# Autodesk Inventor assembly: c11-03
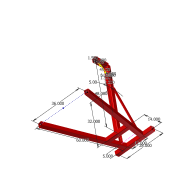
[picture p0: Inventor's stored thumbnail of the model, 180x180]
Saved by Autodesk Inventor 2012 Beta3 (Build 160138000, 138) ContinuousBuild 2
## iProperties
Created: 2011-01
Part Number: c11-03
Document SubType Name: Assembly
Designer: Beta-8540w
_SolveAssemblyDoc: Frame Generator Solve Assembly
_Version: 15.0.0
Author: Beta-8540w
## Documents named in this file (3)
- C:\Inventor 2012 Essentials\Assemblies\Chapter 11\c11-03.iam
- C:\Inventor 2012 Essentials\Parts\Chapter 11\c11-01.ipt
- C:\Inventor 2012 Essentials\Assemblies\Chapter 11\Frame\Frame c11-03.iam
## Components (2 placed, 2 different names)
1. c11-01:1
2. Frame c11-03:1 [sub-assembly]
